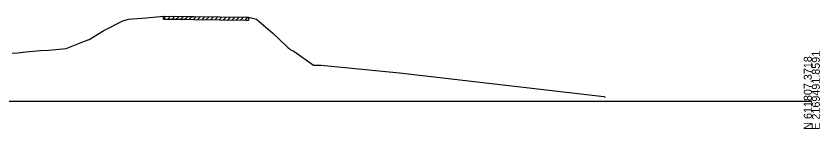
# Model space of a CAD drawing. Extents: x -26 to 6803, y -10 to 19606.
# Drawn here: x 2521.5 to 2802.8, y 4990.3 to 5029.6 of the extents above; entities that cross this region are included whole.
import ezdxf

# ---------------------------------------------------------------- set-up
doc = ezdxf.new("R2010")
doc.units = 0
for name, color, linetype in [('RD_GPK_XS_Cell', 7, 'Continuous'), ('RD_XS_ExGround', 7, 'Continuous'), ('RD_XS_ExPaveRet', 7, 'Continuous'), ('RD_XS_Milling', 7, 'Continuous')]:
    doc.layers.add(name, color=color, linetype=linetype)

msp = doc.modelspace()

# ---------------------------------------------------------------- linework, layer by layer
at = {"layer": 'RD_GPK_XS_Cell'}
msp.add_line((2400, 5000), (2800, 5000), dxfattribs=at)
at = {"layer": 'RD_XS_ExGround'}
msp.add_lwpolyline([(2520.17, 5016.65), (2522.12, 5016.82), (2524.96, 5017.11), (2530.05, 5017.63), (2532.94, 5017.71), (2539.04, 5018.35), (2545.43, 5020.82), (2547.08, 5021.43), (2552.28, 5024.62), (2558.84, 5027.88), (2560.85, 5028.54), (2567.03, 5028.99), (2573.09, 5029.57), (2581.36, 5029.46), (2583.67, 5029.42), (2601.96, 5029.18), (2602.85, 5029.17), (2605.67, 5028.55), (2611.33, 5023.67), (2616.16, 5019.07), (2616.64, 5018.69), (2617, 5018.42), (2617.61, 5017.86), (2618.73, 5017.42), (2625.56, 5012.47), (2626.47, 5012.47), (2627.21, 5012.47), (2628.28, 5012.47), (2655.67, 5009.82), (2727.22, 5001.54), (2727.72, 5001.34)], dxfattribs=at)
at = {"layer": 'RD_XS_ExPaveRet'}
for p, q in [((2573.09, 5028.57), (2573.09, 5029.57)), ((2573.09, 5028.57), (2574.08, 5029.55)), ((2573.09, 5028.57), (2581.36, 5028.46)), ((2574.59, 5028.55), (2575.58, 5029.53)), ((2576.09, 5028.53), (2577.08, 5029.51)), ((2577.59, 5028.51), (2578.58, 5029.49)), ((2579.09, 5028.49), (2580.08, 5029.47)), ((2580.59, 5028.47), (2581.58, 5029.45)), ((2581.36, 5028.46), (2583.67, 5028.42)), ((2582.09, 5028.44), (2583.08, 5029.43)), ((2583.59, 5028.42), (2584.58, 5029.4)), ((2583.67, 5028.42), (2601.96, 5028.18)), ((2585.09, 5028.4), (2586.08, 5029.39)), ((2586.59, 5028.38), (2587.58, 5029.37)), ((2588.09, 5028.36), (2589.08, 5029.35)), ((2589.59, 5028.34), (2590.58, 5029.33)), ((2591.09, 5028.32), (2592.08, 5029.31)), ((2592.59, 5028.3), (2593.58, 5029.29)), ((2594.09, 5028.28), (2595.08, 5029.27)), ((2595.59, 5028.26), (2596.58, 5029.25)), ((2597.09, 5028.24), (2598.08, 5029.23)), ((2598.59, 5028.22), (2599.58, 5029.21)), ((2600.09, 5028.2), (2601.08, 5029.19)), ((2601.59, 5028.18), (2602.58, 5029.17)), ((2601.96, 5028.18), (2602.85, 5028.17)), ((2602.85, 5029.17), (2602.85, 5028.17)), ((2602.85, 5028.17), (2602.85, 5028.17))]:
    msp.add_line(p, q, dxfattribs=at)
at = {"layer": 'RD_XS_Milling'}
msp.add_line((2602.85, 5027.17), (2602.85, 5027.17), dxfattribs=at)
msp.add_line((2602.85, 5027.17), (2602.85, 5027.17), dxfattribs=at)

# ---------------------------------------------------------------- texts
at = {"layer": 'RD_GPK_XS_Cell'}
for s, p in [('E 2169491.8591', (2802.8, 4990)), ('N 611807.3718', (2800, 4990))]:
    msp.add_text(s, height=2.8, rotation=90, dxfattribs=at).set_placement(p)

doc.saveas('drawing.dxf')
